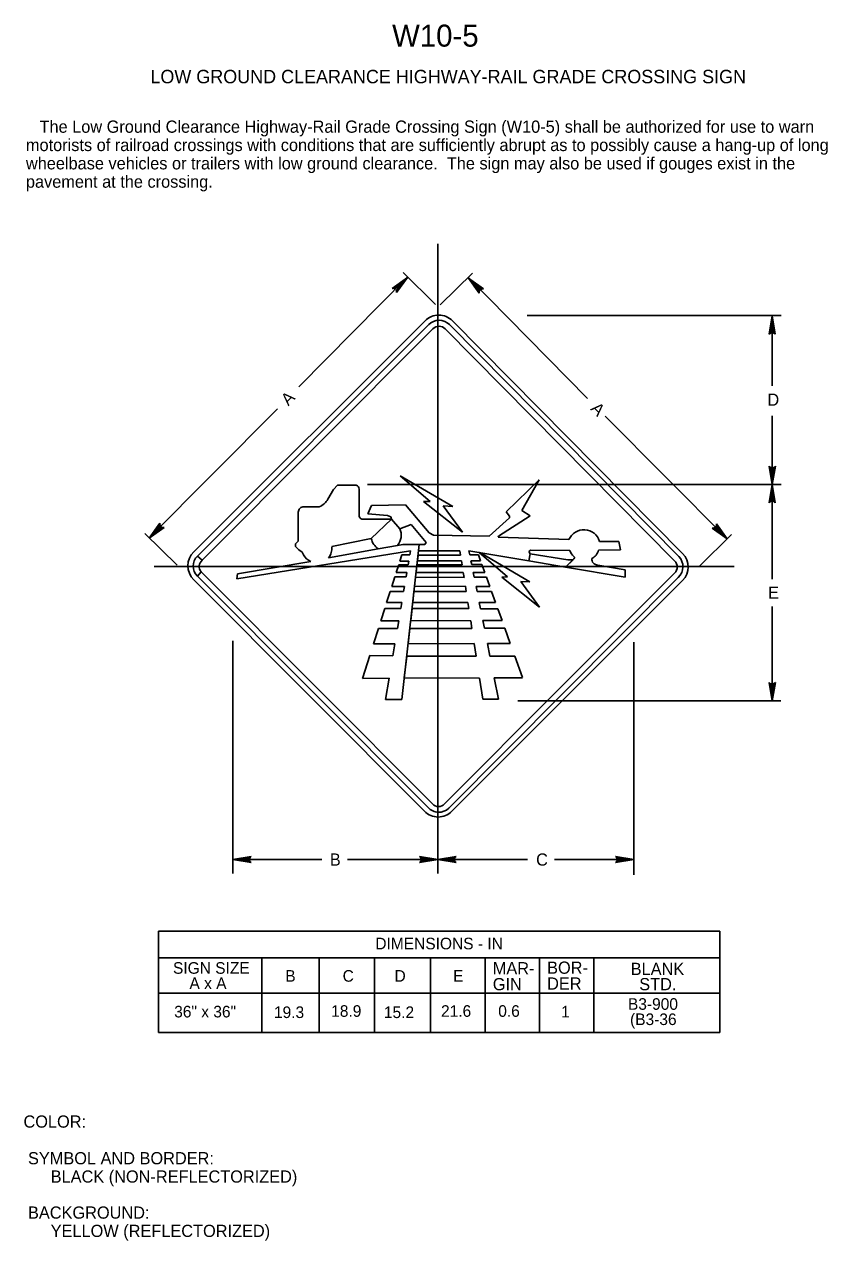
# Model space of a CAD drawing. Extents: x -0.199 to 0.419, y 0.004 to 0.259.
# Drawn here: x 0.0257 to 0.1902, y 0.0101 to 0.2591 of the extents above; entities that cross this region are included whole.
import ezdxf

# ---------------------------------------------------------------- set-up
doc = ezdxf.new("R2010")
doc.units = 0
for name, color, linetype in [('1', 7, 'Continuous'), ('2', 7, 'Continuous'), ('3', 7, 'Continuous'), ('4', 7, 'Continuous'), ('5', 7, 'Continuous')]:
    doc.layers.add(name, color=color, linetype=linetype)

# ---------------------------------------------------------------- blocks, each defined once
blk = doc.blocks.new('RARROW')
at = {"layer": '3'}
for p, q in [((-2.156, 0.28500000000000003), (-2.2665, 0.384625)), ((-2.2665, 0.384625), (0, 0)), ((0, 0), (-2.2665, -0.379125)), ((-2.156, 0.28500000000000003), (-2.075625, 0.12075)), ((0, 0), (-2.156, 0.28500000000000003)), ((-2.14975, -0.2705), (0, 0)), ((-2.075625, 0.12075), (0, 0)), ((0, 0), (-2.074, -0.108)), ((-2.2665, -0.379125), (-2.14975, -0.2705)), ((-2.074, -0.108), (-2.14975, -0.2705))]:
    blk.add_line(p, q, dxfattribs=at)

msp = doc.modelspace()

# ---------------------------------------------------------------- linework, layer by layer
at = {"layer": '1'}
for p, q in [((0.110375, 0.08525), (0.110375, 0.214125)), ((0.12865911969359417, 0.19948563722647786), (0.18065911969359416, 0.19948563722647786)), ((0.09599129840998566, 0.1648794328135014), (0.18065911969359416, 0.1648794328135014)), ((0.052284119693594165, 0.1480906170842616), (0.17103411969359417, 0.1480906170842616)), ((0.068375, 0.08525), (0.068375, 0.132875)), ((0.1505, 0.085), (0.1505, 0.132625)), ((0.12675, 0.120625), (0.180625, 0.120625)), ((0.068375, 0.088125), (0.08662500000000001, 0.088125)), ((0.091875, 0.088125), (0.110375, 0.088125)), ((0.110375, 0.088125), (0.12875, 0.088125)), ((0.13425, 0.088125), (0.1505, 0.088125))]:
    msp.add_line(p, q, dxfattribs=at)
at = {"layer": '3'}
for p, q in [((0.081875, 0.184875), (0.104125, 0.207375)), ((0.109875, 0.20175), (0.10325000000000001, 0.20825)), ((0.110875, 0.201625), (0.11750000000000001, 0.208125)), ((0.14100000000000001, 0.1825), (0.116625, 0.20725000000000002)), ((0.178875, 0.18510497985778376), (0.178875, 0.19948563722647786)), ((0.060375, 0.151125), (0.10775, 0.198375)), ((0.1085, 0.197625), (0.061125, 0.15025)), ((0.062125, 0.149375), (0.109375, 0.19675)), ((0.111875, 0.19675), (0.15887500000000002, 0.14925)), ((0.15975, 0.150125), (0.11275, 0.197625)), ((0.113375, 0.198375), (0.1605, 0.15075)), ((0.0775, 0.180375), (0.051250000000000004, 0.154)), ((0.144625, 0.178875), (0.169625, 0.15375)), ((0.178875, 0.164875), (0.178875, 0.1789575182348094)), ((0.08900912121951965, 0.16385926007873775), (0.08980086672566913, 0.16473945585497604)), ((0.08980086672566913, 0.16473945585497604), (0.09366873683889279, 0.16473945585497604)), ((0.178875, 0.1455), (0.178875, 0.164875)), ((0.08784214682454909, 0.1619057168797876), (0.08900912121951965, 0.16385926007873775)), ((0.09428741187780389, 0.1639472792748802), (0.09428741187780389, 0.15831402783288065)), ((0.08293908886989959, 0.1603384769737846), (0.08609430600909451, 0.1603384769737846)), ((0.08179546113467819, 0.15329691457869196), (0.08179546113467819, 0.15919422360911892)), ((0.0948120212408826, 0.15780883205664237), (0.10087020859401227, 0.15780883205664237)), ((0.10087020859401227, 0.15780883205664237), (0.09674448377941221, 0.15380911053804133)), ((0.10258892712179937, 0.15584061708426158), (0.10087020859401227, 0.15780883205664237)), ((0.057, 0.148375), (0.050375, 0.154875)), ((0.163875, 0.148125), (0.1705, 0.154625)), ((0.08123738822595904, 0.15221806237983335), (0.08124141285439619, 0.15275443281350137)), ((0.08190148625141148, 0.1515386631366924), (0.08123738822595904, 0.15221806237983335)), ((0.08124141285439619, 0.15275443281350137), (0.08179546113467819, 0.15329691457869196)), ((0.09674448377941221, 0.15380911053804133), (0.08868488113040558, 0.1521690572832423)), ((0.09815996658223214, 0.15173669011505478), (0.10213791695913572, 0.15240540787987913)), ((0.10213791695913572, 0.15240540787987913), (0.10322772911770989, 0.15258878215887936)), ((0.10655546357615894, 0.1526010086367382), (0.10299658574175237, 0.12090571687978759)), ((0.10322772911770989, 0.15258878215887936), (0.10655546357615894, 0.1526010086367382)), ((0.061125, 0.15025), (0.062125, 0.149375)), ((0.061125, 0.15025), (0.062125, 0.149375)), ((0.10476658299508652, 0.15130091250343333), (0.06921553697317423, 0.1455511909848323)), ((0.0825897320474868, 0.1510102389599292), (0.08190148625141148, 0.1515386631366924)), ((0.08285275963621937, 0.15047045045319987), (0.0825897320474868, 0.1510102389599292)), ((0.08799221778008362, 0.14986567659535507), (0.09815996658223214, 0.15173669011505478)), ((0.10258956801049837, 0.1492036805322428), (0.10299658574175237, 0.15048028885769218)), ((0.10299658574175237, 0.15048028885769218), (0.10462952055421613, 0.15048609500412)), ((0.10462952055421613, 0.15048609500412), (0.10476658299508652, 0.15130091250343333)), ((0.061875, 0.147), (0.061125, 0.146125)), ((0.061875, 0.147), (0.061125, 0.146125)), ((0.10925, 0.0995), (0.061875, 0.147)), ((0.06930351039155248, 0.1466074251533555), (0.08434663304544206, 0.14915999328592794)), ((0.10184600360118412, 0.14687148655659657), (0.10235113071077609, 0.1484558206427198)), ((0.10235113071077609, 0.1484558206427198), (0.10428814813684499, 0.14845671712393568)), ((0.10441777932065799, 0.14922734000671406), (0.10258956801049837, 0.1492036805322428)), ((0.10428814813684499, 0.14845671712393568), (0.10441777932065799, 0.14922734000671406)), ((0.107625, 0.098), (0.060375, 0.145375)), ((0.061125, 0.146125), (0.108375, 0.09875)), ((0.06921553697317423, 0.1455511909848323), (0.06930351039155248, 0.1466074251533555)), ((0.10092878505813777, 0.14399465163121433), (0.10156543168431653, 0.14599148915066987)), ((0.10156543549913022, 0.14599148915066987), (0.10387276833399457, 0.14598736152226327)), ((0.10402149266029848, 0.14687148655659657), (0.10184600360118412, 0.14687148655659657)), ((0.10387276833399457, 0.14598736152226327), (0.10402149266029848, 0.14687148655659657)), ((0.15887500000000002, 0.14675), (0.11175, 0.0995)), ((0.112625, 0.098625), (0.15962500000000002, 0.145875)), ((0.1605, 0.14525), (0.11325, 0.098)), ((0.09988340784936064, 0.14071583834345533), (0.10061122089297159, 0.14299861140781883)), ((0.10061122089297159, 0.14299861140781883), (0.1033705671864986, 0.1430018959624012)), ((0.10353756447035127, 0.14399465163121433), (0.10092878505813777, 0.14399465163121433)), ((0.1033705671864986, 0.1430018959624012), (0.10353756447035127, 0.14399465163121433)), ((0.09870274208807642, 0.13701268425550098), (0.09948870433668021, 0.13947784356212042)), ((0.09948870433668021, 0.13947784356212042), (0.10277777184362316, 0.13947784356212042)), ((0.10298496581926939, 0.1407095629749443), (0.09988340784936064, 0.14071583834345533)), ((0.10277777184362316, 0.13947784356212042), (0.10298496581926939, 0.1407095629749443)), ((0.178875, 0.120625), (0.178875, 0.13988416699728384)), ((0.10236309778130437, 0.13701268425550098), (0.09870274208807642, 0.13701268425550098)), ((0.10208910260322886, 0.1353838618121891), (0.10236309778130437, 0.13701268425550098)), ((0.09719754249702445, 0.13229163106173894), (0.09818343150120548, 0.1353838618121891)), ((0.09818343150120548, 0.1353838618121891), (0.10208910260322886, 0.1353838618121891)), ((0.10157030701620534, 0.1322997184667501), (0.09719754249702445, 0.13229163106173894)), ((0.10115741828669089, 0.12984516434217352), (0.10157030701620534, 0.1322997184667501)), ((0.09494000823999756, 0.12521087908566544), (0.09642033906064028, 0.12985393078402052)), ((0.09642033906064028, 0.12985393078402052), (0.10115741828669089, 0.12984516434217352)), ((0.10038087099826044, 0.12522878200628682), (0.09494000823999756, 0.12521087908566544)), ((0.0996536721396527, 0.12090571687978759), (0.10038087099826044, 0.12522878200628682)), ((0.10299658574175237, 0.12090571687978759), (0.0996536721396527, 0.12090571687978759)), ((0.110375, 0.08525), (0.110375, 0.090125)), ((0.053125, 0.0735), (0.168125, 0.0735)), ((0.053125, 0.0735), (0.053125, 0.05275)), ((0.168125, 0.0735), (0.168125, 0.05275)), ((0.168125, 0.068), (0.053125, 0.068)), ((0.07433254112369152, 0.06799713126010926), (0.07433254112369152, 0.052701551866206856)), ((0.08608841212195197, 0.06799713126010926), (0.08608841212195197, 0.052747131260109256)), ((0.09738680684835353, 0.06799713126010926), (0.09738680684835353, 0.052747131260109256)), ((0.10883997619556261, 0.06799713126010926), (0.10883997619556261, 0.052747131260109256)), ((0.12008254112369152, 0.06799713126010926), (0.12008254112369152, 0.052701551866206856)), ((0.13120754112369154, 0.06799713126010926), (0.13120754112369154, 0.052701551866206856)), ((0.14233254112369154, 0.06799713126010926), (0.14233254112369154, 0.052701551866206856)), ((0.053125, 0.06075), (0.168125, 0.06075)), ((0.053125, 0.05275), (0.168125, 0.05275))]:
    msp.add_line(p, q, dxfattribs=at)
for centre, radius, start, end in [((0.1105624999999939, 0.19558147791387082), 0.00396407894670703, 44.80603888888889, 135.19396111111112), ((0.11062500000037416, 0.1955143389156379), 0.002995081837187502, 44.80603888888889, 135.19396111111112), ((0.11062500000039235, 0.19550843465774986), 0.001761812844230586, 44.80603888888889, 135.19396111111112), ((0.0933213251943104, 0.163830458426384), 0.000973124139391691, 6.894827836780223, 69.08358465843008), ((0.08495404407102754, 0.1633683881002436), 0.003237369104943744, 290.62308091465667, 333.140185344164), ((0.08292608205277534, 0.15920784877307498), 0.0011307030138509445, 89.34089486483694, 180.6904406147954), ((0.09511982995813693, 0.15865268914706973), 0.0008982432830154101, 201.855216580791, 249.95984913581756), ((0.08516756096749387, 0.15197093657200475), 0.003522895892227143, 323.30229392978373, 2.996632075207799), ((0.0632614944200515, 0.14825000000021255), 0.004073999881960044, 135.11430555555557, 224.88569166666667), ((0.06318991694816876, 0.1481875), 0.0029185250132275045, 135.03355000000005, 224.96644722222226), ((0.06319224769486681, 0.14806200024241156), 0.001692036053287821, 129.1053, 218.8766861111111), ((0.08542803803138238, 0.15189946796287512), 0.002945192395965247, 209.02589608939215, 248.4584196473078), ((0.15756249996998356, 0.1480625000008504), 0.003006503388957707, 313.3153166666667, 43.31531666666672), ((0.15774999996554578, 0.14800000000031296), 0.0038890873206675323, 315, 45), ((0.1576249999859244, 0.14800000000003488), 0.001767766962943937, 315, 45), ((0.1104374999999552, 0.10079974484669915), 0.003968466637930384, 224.86978333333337, 315.1302194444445), ((0.11056221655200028, 0.1008028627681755), 0.002999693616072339, 223.18509722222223, 313.44553333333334), ((0.1105000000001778, 0.10074433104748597), 0.0017637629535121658, 224.86978333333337, 315.1302194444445)]:
    msp.add_arc(centre, radius, start, end, dxfattribs=at)
at = {"layer": '4'}
for p, q in [((0.12435146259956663, 0.1592756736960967), (0.1311003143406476, 0.16586735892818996)), ((0.1311003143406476, 0.16586735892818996), (0.12754557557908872, 0.15953315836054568)), ((0.09604902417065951, 0.1589151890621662), (0.09677027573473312, 0.16056311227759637)), ((0.09677027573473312, 0.16056311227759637), (0.10372519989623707, 0.16071760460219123)), ((0.10372519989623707, 0.16071760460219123), (0.10861940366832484, 0.1550013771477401)), ((0.12754557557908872, 0.15953315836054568), (0.12929718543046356, 0.15850320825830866)), ((0.10006742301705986, 0.15855470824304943), (0.09604902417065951, 0.1589151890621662)), ((0.09674448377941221, 0.15380911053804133), (0.10087020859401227, 0.15780883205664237)), ((0.10073715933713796, 0.158245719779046), (0.10006742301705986, 0.15855470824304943)), ((0.10087020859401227, 0.15780883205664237), (0.10073715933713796, 0.158245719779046)), ((0.12088067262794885, 0.15428040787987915), (0.1250211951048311, 0.15803973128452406)), ((0.12929718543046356, 0.15850320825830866), (0.12280592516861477, 0.1543319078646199)), ((0.1250211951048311, 0.15840021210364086), (0.12435146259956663, 0.1592756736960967)), ((0.1250211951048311, 0.15803973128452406), (0.1250211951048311, 0.15840021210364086)), ((0.10491011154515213, 0.15670079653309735), (0.10258892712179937, 0.15584061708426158)), ((0.10794966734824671, 0.1530444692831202), (0.10491011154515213, 0.15670079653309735)), ((0.10861940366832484, 0.1550013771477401), (0.10949520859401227, 0.15448640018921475)), ((0.10949520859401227, 0.15448640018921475), (0.12088067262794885, 0.15428040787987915)), ((0.10213791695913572, 0.15241763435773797), (0.09815996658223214, 0.15173669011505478)), ((0.10641035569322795, 0.1513087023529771), (0.10655546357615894, 0.1526010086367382)), ((0.10655546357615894, 0.1526010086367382), (0.10769207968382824, 0.15258098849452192)), ((0.10769207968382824, 0.15258098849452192), (0.10794966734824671, 0.1530444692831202)), ((0.12280592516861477, 0.1543319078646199), (0.12270289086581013, 0.15407441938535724)), ((0.12270289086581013, 0.15407441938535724), (0.13721760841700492, 0.1536109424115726)), ((0.14350279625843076, 0.15325045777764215), (0.1474181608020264, 0.1531989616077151)), ((0.1474181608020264, 0.1531989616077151), (0.14777878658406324, 0.15149954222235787)), ((0.10617703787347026, 0.14923074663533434), (0.1063142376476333, 0.15045263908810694)), ((0.1063142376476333, 0.15045263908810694), (0.11503151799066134, 0.1504455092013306)), ((0.11489537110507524, 0.1513301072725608), (0.10641035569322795, 0.1513087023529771)), ((0.11503151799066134, 0.1504455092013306), (0.11489537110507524, 0.1513301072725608)), ((0.12897473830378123, 0.1492851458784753), (0.11675193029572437, 0.15129569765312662)), ((0.11675193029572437, 0.15129569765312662), (0.11690864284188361, 0.1505078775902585)), ((0.11690864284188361, 0.1505078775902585), (0.11867770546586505, 0.1505)), ((0.11867770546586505, 0.1505), (0.11913117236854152, 0.14923825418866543)), ((0.1292939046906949, 0.150720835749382), (0.12897473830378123, 0.1492851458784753)), ((0.1374236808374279, 0.15139654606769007), (0.12933536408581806, 0.1514480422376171)), ((0.13649635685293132, 0.14799770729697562), (0.13824796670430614, 0.1496456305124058)), ((0.13840252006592, 0.14995461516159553), (0.138196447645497, 0.15016060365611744)), ((0.13824796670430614, 0.1496456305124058), (0.13840252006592, 0.14995461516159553)), ((0.14777878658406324, 0.15149954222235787), (0.14329672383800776, 0.1514480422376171)), ((0.10591258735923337, 0.1468755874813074), (0.10608938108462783, 0.148450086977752)), ((0.10608938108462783, 0.148450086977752), (0.11534160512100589, 0.14843074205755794)), ((0.11521847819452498, 0.14923074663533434), (0.10617703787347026, 0.14923074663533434)), ((0.11534160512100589, 0.14843074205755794), (0.11521847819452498, 0.14923074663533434)), ((0.11913117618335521, 0.14923825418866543), (0.11715945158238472, 0.14924703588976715)), ((0.11715945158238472, 0.14924703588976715), (0.11730826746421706, 0.1484989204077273)), ((0.11730826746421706, 0.1484989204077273), (0.11940023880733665, 0.14848960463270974)), ((0.11940023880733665, 0.14848960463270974), (0.1199842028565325, 0.1468647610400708)), ((0.14870611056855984, 0.14588630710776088), (0.13649635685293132, 0.14799770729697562)), ((0.14314217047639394, 0.14840968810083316), (0.14870611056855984, 0.14743123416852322)), ((0.14870611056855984, 0.14743123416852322), (0.14870611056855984, 0.14588630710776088)), ((0.10558912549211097, 0.14399485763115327), (0.10580236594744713, 0.14589396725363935)), ((0.10580236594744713, 0.14589396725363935), (0.11573366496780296, 0.1458833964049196)), ((0.11558134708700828, 0.146873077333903), (0.10591258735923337, 0.1468755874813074)), ((0.11573366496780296, 0.1458833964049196), (0.11558134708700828, 0.146873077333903)), ((0.11998420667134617, 0.1468647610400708), (0.11763333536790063, 0.1468647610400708)), ((0.11763333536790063, 0.1468647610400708), (0.117817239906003, 0.14594024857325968)), ((0.117817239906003, 0.14594024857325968), (0.12031647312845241, 0.14594024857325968)), ((0.12031647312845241, 0.14594024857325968), (0.12100517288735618, 0.14402398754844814)), ((0.10522081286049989, 0.14071467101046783), (0.10547940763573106, 0.14301769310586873)), ((0.10547940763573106, 0.14301769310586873), (0.11617893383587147, 0.1429903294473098)), ((0.11601629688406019, 0.14404705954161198), (0.10558912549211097, 0.14399485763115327)), ((0.11617893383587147, 0.1429903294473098), (0.11601629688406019, 0.14404705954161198)), ((0.12100517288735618, 0.14402398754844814), (0.11819842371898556, 0.14402398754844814)), ((0.11819842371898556, 0.14402398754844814), (0.1184016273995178, 0.14300244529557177)), ((0.1184016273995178, 0.14300244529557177), (0.1213723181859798, 0.14300244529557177)), ((0.12114497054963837, 0.14363501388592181), (0.12113334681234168, 0.14366735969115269)), ((0.1213723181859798, 0.14300244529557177), (0.12218788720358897, 0.14073319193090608)), ((0.10480585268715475, 0.137019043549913), (0.10508176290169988, 0.13947629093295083)), ((0.10508176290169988, 0.13947629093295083), (0.11671864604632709, 0.1394836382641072)), ((0.11652728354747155, 0.14072699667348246), (0.10522081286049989, 0.14071467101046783)), ((0.11671864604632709, 0.1394836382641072), (0.11652728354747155, 0.14072699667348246)), ((0.12218788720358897, 0.14073319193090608), (0.11885303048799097, 0.14073319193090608)), ((0.11885303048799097, 0.14073319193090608), (0.11910715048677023, 0.13945568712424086)), ((0.11910715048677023, 0.13945568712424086), (0.12264701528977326, 0.13945568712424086)), ((0.12264701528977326, 0.13945568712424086), (0.12351926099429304, 0.13702872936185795)), ((0.11709892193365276, 0.13701285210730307), (0.10480585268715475, 0.137019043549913)), ((0.11734369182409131, 0.13542250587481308), (0.11709892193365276, 0.13701285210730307)), ((0.12351926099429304, 0.13702872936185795), (0.11958992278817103, 0.13702872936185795)), ((0.11958992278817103, 0.13702872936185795), (0.1198966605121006, 0.13548671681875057)), ((0.10427667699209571, 0.13230621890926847), (0.10462366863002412, 0.13539650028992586)), ((0.10462366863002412, 0.13539650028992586), (0.11734369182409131, 0.13542250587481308)), ((0.1198966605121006, 0.13548671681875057), (0.12406743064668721, 0.13550348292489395)), ((0.12406743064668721, 0.13550348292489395), (0.12521201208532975, 0.13231876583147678)), ((0.11781478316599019, 0.13236165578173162), (0.10427667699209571, 0.13230621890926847)), ((0.11821238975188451, 0.12977826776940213), (0.11781478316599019, 0.13236165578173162)), ((0.12521201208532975, 0.13231876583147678), (0.12052682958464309, 0.13231876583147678)), ((0.12052682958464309, 0.13231876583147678), (0.12103175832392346, 0.12978041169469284)), ((0.10349420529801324, 0.1253375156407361), (0.10399283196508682, 0.12977826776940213)), ((0.10399283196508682, 0.12977826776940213), (0.11821238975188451, 0.12977826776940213)), ((0.12103175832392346, 0.12978041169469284), (0.12612429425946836, 0.12978041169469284)), ((0.12612429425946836, 0.12978041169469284), (0.12771105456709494, 0.12536537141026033)), ((0.11890882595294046, 0.12525326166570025), (0.10349420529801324, 0.1253375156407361)), ((0.11957078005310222, 0.12095232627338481), (0.11890882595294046, 0.12525326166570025)), ((0.1277389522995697, 0.12528774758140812), (0.12192543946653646, 0.12528774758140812)), ((0.12192543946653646, 0.12528774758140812), (0.12278784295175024, 0.12095232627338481)), ((0.12278784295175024, 0.12095232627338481), (0.11957078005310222, 0.12095232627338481))]:
    msp.add_line(p, q, dxfattribs=at)
for centre, radius, start, end in [((0.09955665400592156, 0.15449894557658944), 0.003315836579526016, 321.1202408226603, 23.867655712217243), ((0.14029312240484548, 0.15226112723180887), 0.0033586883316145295, 17.13108387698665, 156.30376562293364), ((0.09990060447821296, 0.15444517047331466), 0.0032195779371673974, 191.39431589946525, 237.27266516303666), ((0.1295122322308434, 0.15107317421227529), 0.0004144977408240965, 115.25861729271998, 238.2154042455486), ((0.1401967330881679, 0.15227082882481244), 0.002907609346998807, 197.49891165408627, 226.53206779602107), ((0.1431232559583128, 0.14963257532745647), 0.0012230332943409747, 174.555209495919, 270.88617322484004), ((0.14079034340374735, 0.15208055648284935), 0.002584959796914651, 295.5624801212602, 345.8364756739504)]:
    msp.add_arc(centre, radius, start, end, dxfattribs=at)
at = {"layer": '5'}
for p, q in [((0.10264435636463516, 0.16663340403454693), (0.11341896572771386, 0.1604064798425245)), ((0.10882650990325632, 0.16137805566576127), (0.10264435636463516, 0.16663340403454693)), ((0.11545024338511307, 0.15510696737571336), (0.1074134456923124, 0.16137805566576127)), ((0.1074134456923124, 0.16137805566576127), (0.10882650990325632, 0.16137805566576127)), ((0.11341896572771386, 0.1604064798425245), (0.11147600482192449, 0.16049480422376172)), ((0.11147600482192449, 0.16049480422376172), (0.11545024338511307, 0.15510696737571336)), ((0.11884390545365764, 0.15095158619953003), (0.1191234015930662, 0.15090494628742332)), ((0.1246547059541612, 0.1459625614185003), (0.11884390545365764, 0.15095158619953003)), ((0.11884390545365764, 0.15095158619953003), (0.11912339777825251, 0.150904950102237)), ((0.11912339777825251, 0.150904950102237), (0.129221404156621, 0.1449708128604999)), ((0.12897473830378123, 0.1492851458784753), (0.1292939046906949, 0.150720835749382)), ((0.1292939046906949, 0.150720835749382), (0.1370063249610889, 0.14948609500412)), ((0.13807885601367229, 0.14948609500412), (0.13649635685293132, 0.14799770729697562)), ((0.1370063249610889, 0.14948609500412), (0.13807885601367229, 0.14948609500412)), ((0.13649635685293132, 0.14799770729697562), (0.12897473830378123, 0.1492851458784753)), ((0.12344587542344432, 0.14591213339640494), (0.1246547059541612, 0.1459625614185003)), ((0.13121933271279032, 0.13979354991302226), (0.12344587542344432, 0.14591213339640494)), ((0.129221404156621, 0.1449708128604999), (0.12739136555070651, 0.1450044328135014)), ((0.12739136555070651, 0.1450044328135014), (0.13121933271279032, 0.13979354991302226))]:
    msp.add_line(p, q, dxfattribs=at)

# ---------------------------------------------------------------- block references
at = {"layer": '3'}
for p, xscale, yscale, rotation in [((0.104125, 0.20725000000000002), 0.001654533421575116, 0.0016366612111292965, 45.25314611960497), ((0.116625, 0.207125), 0.001654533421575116, 0.0016366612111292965, 134.74685388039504), ((0.178875, 0.199375), 0.0016545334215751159, 0.0016366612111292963, 90), ((0.178875, 0.164875), 0.0016545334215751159, 0.0016366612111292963, -90), ((0.178875, 0.164875), 0.0016545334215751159, 0.0016366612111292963, 90), ((0.051250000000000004, 0.153875), 0.0016545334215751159, 0.0016366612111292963, -134.74685388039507), ((0.169625, 0.15375), 0.0016545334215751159, 0.0016366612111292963, -45.25314611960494), ((0.178875, 0.120625), 0.0016545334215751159, 0.0016366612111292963, -90), ((0.068375, 0.088125), 0.0016545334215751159, 0.0016366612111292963, 180), ((0.110375, 0.088125), 0.0016545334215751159, -0.0016366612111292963, -180)]:
    msp.add_blockref('RARROW', p, dxfattribs=dict(at, xscale=xscale, yscale=yscale, rotation=rotation))
at = {"layer": '3', "xscale": 0.0016545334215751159}
for p, yscale in [((0.110375, 0.088125), -0.0016366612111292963), ((0.1505, 0.088125), 0.0016366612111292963)]:
    msp.add_blockref('RARROW', p, dxfattribs=dict(at, yscale=yscale))

# ---------------------------------------------------------------- texts
at = {"layer": '1'}
for s, height, p in [('W10-5', 0.0045000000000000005, (0.101, 0.2545)), ('LOW GROUND CLEARANCE HIGHWAY-RAIL GRADE CROSSING SIGN', 0.00275025, (0.051500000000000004, 0.247)), ('COLOR:', 0.0024997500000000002, (0.025500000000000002, 0.03325)), (' SYMBOL AND BORDER:', 0.0024997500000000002, (0.025500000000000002, 0.025750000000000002)), ('      BLACK (NON-REFLECTORIZED)', 0.0024997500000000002, (0.025500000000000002, 0.022)), (' BACKGROUND:', 0.0024997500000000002, (0.025500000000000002, 0.014625)), ('      YELLOW (REFLECTORIZED)', 0.0024997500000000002, (0.025500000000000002, 0.010875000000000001))]:
    msp.add_text(s, height=height, dxfattribs=at).set_placement(p)
at = {"layer": '2'}
for s, p in [('   The Low Ground Clearance Highway-Rail Grade Crossing Sign (W10-5) shall be authorized for use to warn', (0.026000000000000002, 0.236875)), ('motorists of railroad crossings with conditions that are sufficiently abrupt as to possibly cause a hang-up of long', (0.026000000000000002, 0.233125)), ('wheelbase vehicles or trailers with low ground clearance.  The sign may also be used if gouges exist in the', (0.026000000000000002, 0.229375)), ('pavement at the crossing.', (0.026000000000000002, 0.225625))]:
    msp.add_text(s, height=0.0024997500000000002, dxfattribs=at).set_placement(p)
at = {"layer": '3'}
for rotation, p in [(45.253147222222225, (0.07975, 0.180875)), (314.7468527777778, (0.14150000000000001, 0.18025))]:
    msp.add_text('A', height=0.0024997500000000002, rotation=rotation, dxfattribs=at).set_placement(p)
for s, height, p in [('D', 0.0024997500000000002, (0.177875, 0.181)), ('E', 0.0024997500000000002, (0.178, 0.14150000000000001)), ('B', 0.0024997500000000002, (0.08825, 0.08687500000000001)), ('C', 0.0024997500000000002, (0.1305, 0.08687500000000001)), ('DIMENSIONS - IN', 0.0023752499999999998, (0.09756659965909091, 0.06975)), ('BOR-', 0.0024997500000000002, (0.13275, 0.06475)), ('SIGN SIZE', 0.0023752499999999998, (0.056125, 0.06475)), ('B', 0.0023752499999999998, (0.079125, 0.063125)), ('C', 0.0023752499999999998, (0.090875, 0.063125)), ('D', 0.0023752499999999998, (0.1015, 0.063125)), ('E', 0.0023752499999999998, (0.1135, 0.063125)), ('MAR-', 0.0024997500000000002, (0.121625, 0.064625)), ('BLANK', 0.0024997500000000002, (0.149875, 0.0645)), ('A x A', 0.0023752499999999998, (0.059500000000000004, 0.061625)), ('GIN', 0.0024997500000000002, (0.121625, 0.061375)), ('DER', 0.0024997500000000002, (0.13275, 0.0615)), ('STD.', 0.0024997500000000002, (0.151625, 0.061375)), ('B3-900', 0.0023752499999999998, (0.1493106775, 0.057375)), ('36" x 36"', 0.0023752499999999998, (0.05637041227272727, 0.055812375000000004)), ('19.3', 0.0023752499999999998, (0.07680828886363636, 0.055687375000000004)), ('18.9', 0.0023752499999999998, (0.08852733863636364, 0.055937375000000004)), ('15.2', 0.0023752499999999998, (0.09932520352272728, 0.055687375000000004)), ('21.6', 0.0023752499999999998, (0.11102373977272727, 0.055937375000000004)), ('0.6', 0.0023752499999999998, (0.1227435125, 0.055937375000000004)), ('1', 0.0023752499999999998, (0.13564395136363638, 0.055812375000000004)), ('(B3-36', 0.0023752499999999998, (0.14974146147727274, 0.05424975))]:
    msp.add_text(s, height=height, dxfattribs=at).set_placement(p)

doc.saveas('drawing.dxf')
